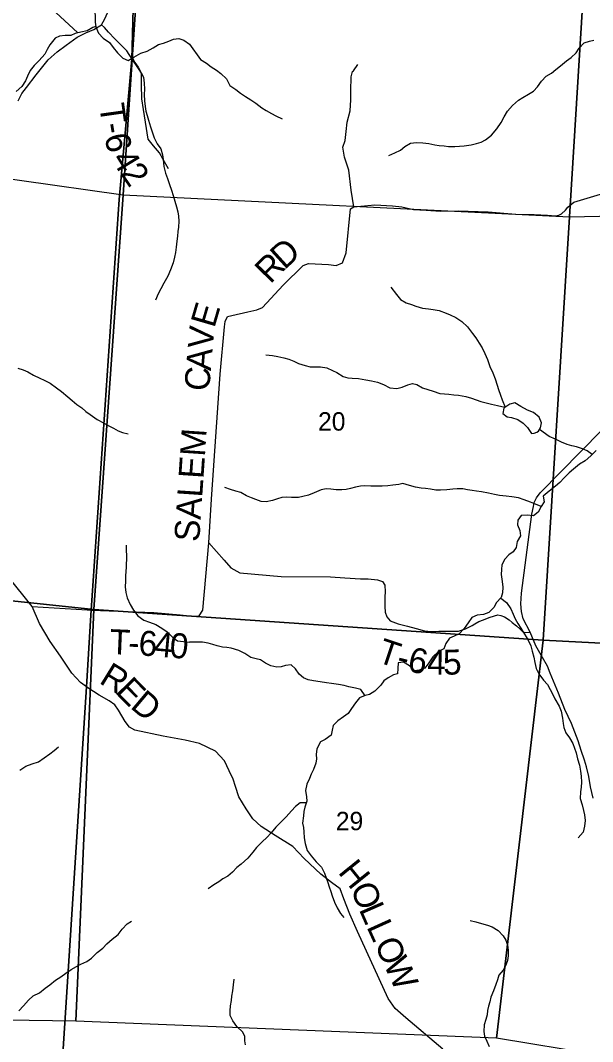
# Model space of a CAD drawing. Extents: x 0 to 40.8, y 0 to 22.
# Drawn here: x 3.414 to 4.714, y 18.326 to 20.647 of the extents above; entities that cross this region are included whole.
import ezdxf

# ---------------------------------------------------------------- set-up
doc = ezdxf.new("R2010")
doc.units = 0
for name, color, linetype in [('Default', 7, 'Continuous'), ('GM_X_County_Road', 7, 'Continuous'), ('GM_X_County_Road_Text', 7, 'Continuous'), ('GM_X_Minor_Lake', 7, 'Continuous'), ('GM_X_Minor_River', 7, 'Continuous'), ('GM_X_Section', 7, 'Continuous'), ('GM_X_Section_Text', 7, 'Continuous'), ('GM_X_State_Route', 7, 'Continuous'), ('GM_X_Township_Road', 7, 'Continuous'), ('GM_X_Township_Road_Text', 7, 'Continuous')]:
    doc.layers.add(name, color=color, linetype=linetype)

msp = doc.modelspace()

# ---------------------------------------------------------------- linework, layer by layer
at = {"layer": 'Default'}
msp.add_lwpolyline([(3.6829, 20.9), (2.1, 20.9), (2.1, 17.4153), (2.4594, 17.3966), (2.8463, 17.3693), (2.8484, 17.3691), (3.1244, 17.3534), (3.4481, 17.3334), (3.5638, 19.132), (3.5742, 19.2945), (3.575, 19.3064), (3.6386, 20.2396), (3.6672, 20.5588), (3.6703, 20.6733)], close=True, dxfattribs=at)
msp.add_lwpolyline([(7.7204, 20.9), (3.6829, 20.9), (3.6703, 20.6733), (3.6672, 20.5588), (3.6386, 20.2396), (3.575, 19.3064), (3.5742, 19.2945), (3.5638, 19.132), (3.4481, 17.3334), (4.5348, 17.2687), (4.8294, 17.2493), (5.3407, 17.2146), (5.6278, 17.197), (6.1785, 17.166), (6.9172, 17.1197)], dxfattribs=at)
at = {"layer": 'GM_X_County_Road'}
for points in [[(3.6903, 20.9), (2.7446, 20.9), (2.7045, 20.3832), (3.6475, 20.2502)], [(4.7052, 20.9), (3.6903, 20.9), (3.6475, 20.2502), (4.6616, 20.2002)], [(5.7251, 20.9), (4.7052, 20.9), (4.6616, 20.2002), (5.209, 20.2119), (5.6669, 20.1827)]]:
    msp.add_lwpolyline(points, close=True, dxfattribs=at)
for points in [[(3.4084, 20.464), (3.4169, 20.4805), (3.4276, 20.4943), (3.4494, 20.5231), (3.4772, 20.5566), (3.4975, 20.5749), (3.5175, 20.59), (3.5432, 20.6081), (3.5625, 20.6182), (3.5807, 20.6257), (3.5982, 20.6368), (3.606, 20.6499), (3.6118, 20.6641), (3.6169, 20.6889), (3.619, 20.7128), (3.6158, 20.741), (3.6108, 20.78), (3.6063, 20.8149), (3.6057, 20.8342), (3.608, 20.8547), (3.6128, 20.8672), (3.6204, 20.8813), (3.6297, 20.8957), (3.631, 20.9)], [(3.5673, 19.1293), (3.564, 19.1315), (3.5503, 19.1417), (3.531, 19.1627), (3.5049, 19.2019), (3.4817, 19.2352), (3.4576, 19.2755), (3.4403, 19.3142), (3.3856, 19.3835)], [(4.374, 18.3086), (4.29, 18.3799), (4.2657, 18.4005), (4.2493, 18.4238), (4.1803, 18.5758), (4.1625, 18.6154), (4.1492, 18.65), (4.1409, 18.6725), (4.1211, 18.6874), (4.0968, 18.7061), (4.0588, 18.7416), (4.0333, 18.769), (3.9926, 18.7943), (3.9607, 18.8145), (3.9424, 18.8317), (3.9269, 18.8549), (3.9102, 18.882), (3.9026, 18.9052), (3.8973, 18.922), (3.8886, 18.9406), (3.8779, 18.9635), (3.8571, 18.9856), (3.8211, 19.0031), (3.7883, 19.0106), (3.7386, 19.02), (3.6739, 19.0336), (3.6616, 19.04), (3.6522, 19.0528), (3.6371, 19.0785), (3.6287, 19.0907), (3.6152, 19.1004), (3.5929, 19.1126), (3.5673, 19.1293)]]:
    msp.add_lwpolyline(points, dxfattribs=at)
at = {"layer": 'GM_X_Minor_Lake'}
for points in [[(4.5956, 19.7204), (4.5984, 19.7321), (4.5931, 19.7447), (4.5799, 19.755), (4.5663, 19.7604), (4.5513, 19.7688), (4.5377, 19.7773), (4.5259, 19.7743), (4.5126, 19.7656), (4.5099, 19.7531), (4.5201, 19.7455), (4.5299, 19.7443), (4.5443, 19.7393), (4.5563, 19.7313), (4.5665, 19.721), (4.5751, 19.7076)], [(4.5751, 19.7076), (4.5812, 19.7081), (4.5872, 19.7103), (4.5911, 19.7129), (4.5956, 19.7204)]]:
    msp.add_lwpolyline(points, dxfattribs=at)
at = {"layer": 'GM_X_Minor_River'}
for points in [[(3.2517, 20.805), (3.2623, 20.8063), (3.2737, 20.8045), (3.2835, 20.8031), (3.2936, 20.7998), (3.3045, 20.7972), (3.3151, 20.7939), (3.3278, 20.7871), (3.3382, 20.7811), (3.3479, 20.7748), (3.3576, 20.7674), (3.3683, 20.7595), (3.3784, 20.752), (3.39, 20.7464), (3.4, 20.7401), (3.4108, 20.7322), (3.4209, 20.7255), (3.4324, 20.718), (3.4424, 20.7094), (3.4539, 20.7004), (3.4647, 20.691), (3.4747, 20.6824), (3.5442, 20.618)], [(3.5816, 20.6715), (3.5833, 20.6653), (3.5835, 20.6555), (3.584, 20.6422), (3.5849, 20.6319), (3.5911, 20.6174), (3.6019, 20.6061), (3.6165, 20.596), (3.625, 20.5852), (3.6346, 20.5725), (3.6465, 20.5605), (3.6589, 20.5553), (3.6716, 20.563), (3.6873, 20.5722), (3.7018, 20.5768), (3.7152, 20.5842), (3.7279, 20.5915), (3.7389, 20.5947), (3.7511, 20.599), (3.7615, 20.6038), (3.774, 20.6054), (3.7853, 20.6014), (3.798, 20.5924)], [(3.5849, 20.6325), (3.5781, 20.6302), (3.5658, 20.6232), (3.551, 20.6197), (3.538, 20.6165), (3.5281, 20.6125), (3.5152, 20.612), (3.5026, 20.6104), (3.4931, 20.606), (3.4806, 20.5911), (3.4744, 20.5806), (3.4692, 20.57), (3.4568, 20.5551), (3.4452, 20.5443), (3.4359, 20.5324), (3.43, 20.5196), (3.4252, 20.509), (3.417, 20.4967), (3.4039, 20.4848)], [(3.798, 20.5924), (3.8228, 20.5578), (3.8371, 20.549), (3.8477, 20.5414), (3.8598, 20.5333), (3.8696, 20.5261), (3.882, 20.5135), (3.8898, 20.4986), (3.9038, 20.4898), (3.914, 20.4814), (3.9253, 20.4738), (3.9377, 20.4657), (3.9486, 20.4585), (3.9626, 20.4478), (3.9724, 20.442), (3.9848, 20.4351), (3.9947, 20.4297), (4.0086, 20.4232)], [(4.2512, 20.3395), (4.2648, 20.3458), (4.2774, 20.3518), (4.2873, 20.3597), (4.3002, 20.3672), (4.3142, 20.3691), (4.3286, 20.3686), (4.3418, 20.3666), (4.3554, 20.3635), (4.3656, 20.3619), (4.3766, 20.3611), (4.3868, 20.3603), (4.4008, 20.3602), (4.4118, 20.3605), (4.4221, 20.3612), (4.438, 20.3634), (4.4501, 20.3667), (4.4611, 20.3697), (4.4706, 20.3753), (4.4843, 20.3855), (4.4969, 20.4002), (4.5061, 20.4142), (4.5133, 20.4274), (4.521, 20.4406), (4.5324, 20.4535), (4.5457, 20.4651), (4.556, 20.4715), (4.5685, 20.479), (4.5796, 20.4858), (4.5887, 20.4956), (4.5983, 20.5084), (4.6089, 20.5197), (4.6211, 20.5269), (4.631, 20.5352), (4.6413, 20.5431), (4.655, 20.5547), (4.6652, 20.5626), (4.6767, 20.5732), (4.6835, 20.5834), (4.695, 20.5955), (4.7071, 20.5992), (4.7173, 20.6014)], [(3.6687, 20.5613), (3.674, 20.5512), (3.6814, 20.5401), (3.6883, 20.5274), (3.6935, 20.5178), (3.6951, 20.5041), (3.6956, 20.49), (3.6953, 20.4783), (3.6962, 20.4635), (3.6975, 20.4505), (3.6992, 20.4399), (3.7016, 20.4303), (3.7052, 20.42), (3.7098, 20.4044), (3.713, 20.3933), (3.7181, 20.3799), (3.725, 20.3657), (3.7332, 20.3549), (3.7371, 20.3408), (3.738, 20.3306), (3.7396, 20.3146), (3.7435, 20.2993), (3.7478, 20.2871), (3.7528, 20.2737), (3.7571, 20.2607), (3.7607, 20.2489), (3.765, 20.2355), (3.7689, 20.2225), (3.7717, 20.2115), (3.7731, 20.2019), (3.7736, 20.1902), (3.7729, 20.1769), (3.772, 20.167), (3.771, 20.1561), (3.7697, 20.1451), (3.7679, 20.1314), (3.7665, 20.1193), (3.764, 20.1084), (3.7611, 20.0959), (3.7551, 20.0797), (3.7488, 20.0654), (3.7398, 20.0493), (3.7327, 20.0365), (3.7268, 20.0248), (3.7212, 20.0105)], [(4.2554, 20.0399), (4.2685, 20.0235), (4.2779, 20.012), (4.2907, 20.0048), (4.3024, 20.0009), (4.3126, 19.9974), (4.3278, 19.9928), (4.3414, 19.9912), (4.3516, 19.9896), (4.3652, 19.9872), (4.3811, 19.9811), (4.3909, 19.9776), (4.4037, 19.9711), (4.4173, 19.9619), (4.4301, 19.9501), (4.4414, 19.9352), (4.4489, 19.9249), (4.4567, 19.9131), (4.4631, 19.9021), (4.4691, 19.8895), (4.4754, 19.8758), (4.481, 19.8603), (4.4874, 19.8454), (4.493, 19.8317), (4.4974, 19.8173), (4.5004, 19.8074), (4.5048, 19.7949), (4.5089, 19.7842), (4.5154, 19.7674)], [(3.9716, 19.8864), (3.9871, 19.8848), (3.9992, 19.8829), (4.0128, 19.8794), (4.0238, 19.8767), (4.0351, 19.872), (4.046, 19.867), (4.0612, 19.862), (4.0721, 19.8589), (4.0831, 19.8589), (4.096, 19.8592), (4.1104, 19.8568), (4.1228, 19.8507), (4.1326, 19.846), (4.1477, 19.8372), (4.1579, 19.8341), (4.1681, 19.8333), (4.1821, 19.8328), (4.1992, 19.8297), (4.2116, 19.827), (4.2256, 19.8242), (4.2392, 19.8192), (4.2532, 19.8116), (4.2691, 19.8096), (4.2812, 19.8129), (4.2945, 19.8185), (4.3047, 19.8211), (4.3146, 19.8188), (4.3278, 19.8115), (4.3399, 19.808), (4.3519, 19.8038), (4.3667, 19.7984), (4.3773, 19.7976), (4.3875, 19.7967), (4.3992, 19.7959), (4.4094, 19.7947), (4.4265, 19.7916), (4.4393, 19.7881), (4.4499, 19.7842), (4.4601, 19.7807), (4.4726, 19.7776), (4.4843, 19.7745), (4.4983, 19.771), (4.515, 19.7672)], [(3.4081, 19.8561), (3.4201, 19.8525), (3.4307, 19.8481), (3.4438, 19.8406), (3.4577, 19.8335), (3.4675, 19.8288), (3.4817, 19.8224), (3.4956, 19.8115), (3.5075, 19.8033), (3.5213, 19.7913), (3.5318, 19.7827), (3.5422, 19.7738), (3.5531, 19.766), (3.5628, 19.7578), (3.5725, 19.7512), (3.5886, 19.7391), (3.6025, 19.7316), (3.616, 19.7241), (3.6257, 19.7194), (3.6362, 19.7139), (3.646, 19.7099), (3.6585, 19.7066)], [(4.7136, 19.6601), (4.7017, 19.6686), (4.6915, 19.6728), (4.6775, 19.6771), (4.6669, 19.6794), (4.6563, 19.6825), (4.6439, 19.6879), (4.6299, 19.6944), (4.6156, 19.7009), (4.5935, 19.7169)], [(4.7221, 19.6688), (4.7103, 19.6568), (4.697, 19.6455), (4.6841, 19.638), (4.6711, 19.6267), (4.6609, 19.6184), (4.6498, 19.6067), (4.6399, 19.5965), (4.6296, 19.5882), (4.6156, 19.5762), (4.6019, 19.5653), (4.604, 19.5527), (4.5975, 19.5421), (4.5903, 19.5285), (4.58, 19.5203), (4.5652, 19.5219), (4.552, 19.5212), (4.544, 19.5106), (4.5439, 19.5004), (4.5487, 19.4875), (4.5506, 19.4753), (4.5429, 19.4621), (4.5406, 19.4488), (4.5337, 19.439), (4.5238, 19.4315), (4.5146, 19.4217), (4.5077, 19.4092), (4.5069, 19.3986), (4.5065, 19.3872), (4.509, 19.3716), (4.5101, 19.3584), (4.5092, 19.3455), (4.5065, 19.3349), (4.4955, 19.3239), (4.4901, 19.3122), (4.4787, 19.3005), (4.4662, 19.2961), (4.4521, 19.2946), (4.4396, 19.2898), (4.4312, 19.2773), (4.422, 19.2645), (4.411, 19.2524), (4.3996, 19.2468), (4.3893, 19.2423), (4.3809, 19.2302), (4.3759, 19.2185), (4.3634, 19.2117), (4.3508, 19.2), (4.342, 19.1864), (4.3329, 19.1744), (4.32, 19.1699), (4.3086, 19.1684), (4.2985, 19.1799), (4.2845, 19.1879), (4.2724, 19.1861), (4.2719, 19.1732), (4.2711, 19.1615), (4.2616, 19.1589), (4.2495, 19.1525), (4.2399, 19.1457), (4.2327, 19.1359), (4.2197, 19.1219), (4.2072, 19.1144), (4.1977, 19.1118), (4.1848, 19.1066), (4.1756, 19.0953), (4.1665, 19.0824), (4.1588, 19.0715), (4.1478, 19.0636), (4.1353, 19.0549), (4.1246, 19.044), (4.1223, 19.033), (4.1203, 19.0217), (4.1062, 19.0119), (4.096, 19.0066), (4.0875, 18.9908), (4.0863, 18.9779)], [(4.5973, 19.5417), (4.5847, 19.5468), (4.5734, 19.5518), (4.5586, 19.5572), (4.5462, 19.5618), (4.5307, 19.5638), (4.5178, 19.565), (4.5027, 19.567), (4.4913, 19.5693), (4.4773, 19.5717), (4.4618, 19.5748), (4.4501, 19.5768), (4.4403, 19.5784), (4.4297, 19.5799), (4.4195, 19.5819), (4.4066, 19.582), (4.3968, 19.5813), (4.3827, 19.5798), (4.3687, 19.5788), (4.3577, 19.5789), (4.346, 19.5808), (4.3347, 19.5824), (4.3245, 19.5832), (4.3116, 19.5856), (4.2984, 19.5894), (4.2832, 19.5937), (4.2738, 19.5919), (4.2605, 19.5904), (4.2488, 19.589), (4.2359, 19.5879), (4.2226, 19.5876), (4.2101, 19.5877), (4.1969, 19.5885), (4.187, 19.5882), (4.1753, 19.586), (4.1639, 19.583), (4.1544, 19.5801), (4.1442, 19.5794), (4.1313, 19.5794), (4.1196, 19.5814), (4.109, 19.5819), (4.0973, 19.5797), (4.0813, 19.5725), (4.0684, 19.5673), (4.0555, 19.5644), (4.046, 19.5621), (4.0298, 19.5622), (4.0184, 19.5631), (4.0082, 19.5624), (3.9979, 19.5594), (3.9866, 19.5557), (3.9725, 19.5523), (3.9608, 19.5532), (3.9487, 19.5578), (3.9389, 19.5616), (3.9279, 19.5663), (3.9147, 19.5732), (3.9034, 19.5766), (3.8913, 19.5805), (3.8785, 19.5848)], [(3.6544, 19.4539), (3.6545, 19.4436), (3.6546, 19.4288), (3.6541, 19.4038), (3.6536, 19.3943), (3.653, 19.3841), (3.6524, 19.3723), (3.6522, 19.3594), (3.6534, 19.3465), (3.6566, 19.3339), (3.6635, 19.3193), (3.6708, 19.3063), (3.6808, 19.2936), (3.6943, 19.2834), (3.7071, 19.2786), (3.7214, 19.2734), (3.7349, 19.2655), (3.7476, 19.2566), (3.7599, 19.2438), (3.7707, 19.2364), (3.7843, 19.2346), (3.7983, 19.2332)], [(4.5054, 19.3337), (4.5182, 19.3238), (4.5283, 19.3093), (4.5339, 19.2968), (4.5384, 19.2861), (4.544, 19.2755), (4.5508, 19.2652), (4.5598, 19.2519), (4.5673, 19.2393), (4.5736, 19.2249), (4.5769, 19.2131), (4.581, 19.1994), (4.5828, 19.1873), (4.5862, 19.1732), (4.5921, 19.1614), (4.6027, 19.1473), (4.6117, 19.137), (4.6177, 19.126), (4.6229, 19.1157), (4.6285, 19.1043), (4.6379, 19.0876), (4.6431, 19.0769), (4.646, 19.0606), (4.6475, 19.0488), (4.6489, 19.0394), (4.6534, 19.0276), (4.6617, 19.0162), (4.6692, 19.0028), (4.6733, 18.9926), (4.6766, 18.9816), (4.6803, 18.9683), (4.6847, 18.9538), (4.6869, 18.9402), (4.688, 18.9288), (4.6891, 18.9155), (4.6882, 18.9041), (4.6866, 18.8931), (4.6858, 18.8783), (4.6902, 18.8635), (4.6932, 18.851), (4.6958, 18.8411), (4.6972, 18.8278), (4.696, 18.815), (4.6925, 18.8017), (4.6818, 18.7885)], [(4.197, 19.1115), (4.1876, 19.1256), (4.1755, 19.129), (4.1604, 19.1322), (4.1498, 19.1349), (4.1369, 19.1369), (4.121, 19.1392), (4.1097, 19.1408), (4.0953, 19.1432), (4.0798, 19.1452), (4.0677, 19.1475), (4.0575, 19.1525), (4.0477, 19.1609), (4.0391, 19.1727), (4.0289, 19.1815), (4.0164, 19.1804), (4.0065, 19.1775), (3.9963, 19.1764), (3.9827, 19.1795), (3.971, 19.186), (3.9597, 19.1929), (3.9495, 19.1952), (3.9378, 19.1987), (3.9242, 19.2075), (3.9106, 19.2144), (3.8928, 19.2195), (3.883, 19.221), (3.8732, 19.2222), (3.8611, 19.2253), (3.8513, 19.2281), (3.8407, 19.2312), (3.8278, 19.2335), (3.7983, 19.2332)], [(3.4125, 18.9428), (3.4259, 18.9513), (3.4404, 18.9571), (3.4553, 18.9617), (3.468, 18.9702), (3.4807, 18.9794), (3.4903, 18.9872), (3.5007, 18.9954)], [(4.0863, 18.9779), (4.0866, 18.9684), (4.0854, 18.9582), (4.0801, 18.9438), (4.0747, 18.9336), (4.0705, 18.9237), (4.0647, 18.9109), (4.0616, 18.8961), (4.0641, 18.8821), (4.0645, 18.8718), (4.0606, 18.8582), (4.0579, 18.8484), (4.0571, 18.8385), (4.0551, 18.8218), (4.0573, 18.8123), (4.0576, 18.8021), (4.0586, 18.7884), (4.0612, 18.7755), (4.0653, 18.7599), (4.0743, 18.7478), (4.0859, 18.734), (4.0984, 18.7218), (4.1051, 18.7085), (4.1122, 18.6869), (4.1155, 18.677), (4.1192, 18.6663), (4.1226, 18.6565), (4.1278, 18.6428), (4.1338, 18.6295), (4.1416, 18.6169), (4.1491, 18.6074)], [(4.0635, 18.8683), (4.0493, 18.8681), (4.039, 18.8602), (4.0303, 18.85), (4.0177, 18.8361), (3.9944, 18.8131), (3.9841, 18.7999), (3.9742, 18.7893), (3.9636, 18.7795), (3.9502, 18.7667), (3.9418, 18.7561), (3.9304, 18.7426), (3.9155, 18.729), (3.9056, 18.7211), (3.8957, 18.7109), (3.8855, 18.7019), (3.8741, 18.6951), (3.8646, 18.6887), (3.8532, 18.6816), (3.8402, 18.6729)], [(3.4099, 18.3955), (3.4211, 18.4071), (3.4319, 18.4198), (3.4428, 18.4298), (3.4569, 18.4367), (3.47, 18.4467), (3.4808, 18.4549), (3.4935, 18.4652), (3.5058, 18.4726), (3.5169, 18.4811), (3.5292, 18.4892), (3.5411, 18.4962), (3.5514, 18.5017), (3.5645, 18.5079), (3.5752, 18.5149), (3.5883, 18.5279), (3.6014, 18.5379), (3.6103, 18.548), (3.6227, 18.558), (3.6358, 18.5687), (3.6451, 18.5811), (3.6563, 18.593), (3.6663, 18.5992)], [(4.4357, 18.6011), (4.4489, 18.5976), (4.4618, 18.5937), (4.4754, 18.5899), (4.486, 18.586), (4.4995, 18.5784), (4.5108, 18.5658), (4.5172, 18.5559), (4.5209, 18.5449), (4.5227, 18.5335), (4.5227, 18.5202), (4.5207, 18.51), (4.5172, 18.499), (4.5111, 18.488), (4.5012, 18.4763), (4.4981, 18.4657), (4.4946, 18.4555), (4.4892, 18.4411), (4.4831, 18.4264), (4.4804, 18.4162), (4.4773, 18.4063), (4.4757, 18.3965), (4.4745, 18.3866), (4.4718, 18.3756), (4.4679, 18.3639), (4.4667, 18.3484), (4.4689, 18.3377), (4.4741, 18.3263), (4.4794, 18.3145)], [(3.9255, 18.3178), (3.924, 18.3273), (3.9237, 18.3372), (3.9196, 18.3467), (3.9057, 18.3597), (3.8963, 18.3726), (3.8907, 18.3852), (3.8904, 18.3954), (3.8912, 18.4068), (3.8935, 18.4193), (3.8944, 18.4288), (3.8963, 18.4409), (3.8979, 18.4545)], [(3.8979, 18.4545), (3.8995, 18.4674)]]:
    msp.add_lwpolyline(points, dxfattribs=at)
at = {"layer": 'GM_X_Section'}
for points in [[(2.7045, 20.3832), (3.6475, 20.2502), (3.5805, 19.3077), (2.6264, 19.4085)], [(3.6475, 20.2502), (4.6616, 20.2002), (4.6019, 19.2378), (3.5805, 19.3077)], [(4.6616, 20.2002), (5.209, 20.2119), (5.6669, 20.1827), (5.5995, 19.1863), (4.6019, 19.2378)], [(2.6264, 19.4085), (3.5805, 19.3077), (3.54, 18.3719), (2.5343, 18.3862)], [(3.5805, 19.3077), (4.6019, 19.2378), (4.4961, 18.3336), (3.54, 18.3719)]]:
    msp.add_lwpolyline(points, close=True, dxfattribs=at)
msp.add_lwpolyline([(5.1222, 18.2458), (4.9546, 18.2574), (4.4961, 18.3336), (4.6019, 19.2378), (5.5995, 19.1863), (5.5864, 18.978)], dxfattribs=at)
at = {"layer": 'GM_X_State_Route'}
msp.add_lwpolyline([(4.7157, 18.8789), (4.7097, 18.9044), (4.7057, 18.9284), (4.7006, 18.9497), (4.6961, 18.965), (4.6886, 18.9874), (4.6812, 19.0088), (4.6666, 19.0488), (4.6512, 19.0801), (4.637, 19.1178), (4.6176, 19.1628), (4.612, 19.1785), (4.6007, 19.1987), (4.5853, 19.2247), (4.5726, 19.2559), (4.5561, 19.2861), (4.5524, 19.3032), (4.5514, 19.3204), (4.5527, 19.3451), (4.5763, 19.5243), (4.5802, 19.5414), (4.5814, 19.5505), (4.5864, 19.5615), (4.5949, 19.5728), (4.8739, 19.8562)], dxfattribs=at)
at = {"layer": 'GM_X_Township_Road'}
msp.add_line((3.4403, 19.3142), (3.5656, 19.3065), dxfattribs=at)
for points in [[(3.6675, 20.5583), (3.6555, 20.5777), (3.6282, 20.6045), (3.6141, 20.6199), (3.605, 20.6301), (3.5982, 20.6368)], [(3.7505, 20.3089), (3.7381, 20.3307), (3.7298, 20.3459), (3.7166, 20.3612), (3.7045, 20.3768), (3.6979, 20.4152), (3.6935, 20.4442), (3.6899, 20.4685), (3.6894, 20.5011), (3.6894, 20.5264), (3.6826, 20.5373), (3.6675, 20.5583)], [(4.1718, 20.2232), (4.1654, 20.2605), (4.1601, 20.3061), (4.1507, 20.3354), (4.1469, 20.3583), (4.1522, 20.3739), (4.1542, 20.394), (4.1565, 20.4149), (4.1634, 20.4411), (4.1649, 20.4662), (4.165, 20.4868), (4.1654, 20.518), (4.1686, 20.5307), (4.1706, 20.5322), (4.181, 20.5461)], [(3.5656, 19.3065), (3.5753, 19.3059), (3.7167, 19.3008), (3.7773, 19.2954), (3.806, 19.2924), (3.8202, 19.2934), (3.8286, 19.3063), (3.8422, 19.4588), (3.8484, 19.5585), (3.8675, 19.8425), (3.8776, 19.9498), (3.8795, 19.9619), (3.8848, 19.9733), (3.894, 19.9756), (3.9309, 19.9842), (3.9511, 19.9884), (3.964, 19.994), (4.0109, 20.0445), (4.0563, 20.0896), (4.0685, 20.0941), (4.1141, 20.0921), (4.1316, 20.0898), (4.1461, 20.0954), (4.1545, 20.1186), (4.1642, 20.2179), (4.1718, 20.2232), (4.2194, 20.2272), (4.2593, 20.2248), (4.281, 20.2225), (4.3073, 20.2167), (4.3358, 20.2155), (4.3682, 20.2131), (4.4089, 20.2137), (4.477, 20.2112), (4.5398, 20.2061), (4.5816, 20.2052), (4.6121, 20.2036), (4.6296, 20.2021), (4.6376, 20.2036), (4.6437, 20.2066), (4.6528, 20.2153), (4.6578, 20.2221), (4.6715, 20.2331), (4.732, 20.2516)], [(3.8422, 19.4588), (3.8771, 19.4195), (3.8919, 19.402), (3.9129, 19.3913), (4.0068, 19.383), (4.1187, 19.3816), (4.1515, 19.3799), (4.1869, 19.3772), (4.2044, 19.3775), (4.2253, 19.3748), (4.2371, 19.3709), (4.2424, 19.3629), (4.2431, 19.3481), (4.2424, 19.3363), (4.2419, 19.3143), (4.2431, 19.3017), (4.2465, 19.2907), (4.2544, 19.2815), (4.2723, 19.2754), (4.2936, 19.2696), (4.313, 19.2646), (4.3324, 19.2592), (4.3473, 19.2573), (4.3648, 19.258), (4.38, 19.2587), (4.3975, 19.2583), (4.4093, 19.2586), (4.4257, 19.2635), (4.4409, 19.2715), (4.4466, 19.2752), (4.4558, 19.2802), (4.4664, 19.2843), (4.4794, 19.2892), (4.4916, 19.293), (4.4992, 19.2956), (4.506, 19.2941), (4.5144, 19.291), (4.5243, 19.2841), (4.5315, 19.278), (4.5414, 19.2704), (4.5486, 19.2635), (4.5558, 19.257), (4.5612, 19.2551), (4.5726, 19.2559)]]:
    msp.add_lwpolyline(points, dxfattribs=at)

# ---------------------------------------------------------------- texts
at = {"layer": 'GM_X_County_Road_Text'}
for s, rotation, p in [('R', 328.2751, (3.5905, 19.1417)), ('E', 314.5061, (3.6274, 19.1194)), ('D', 319.8874, (3.6614, 19.0852)), ('H', 308.9511, (4.1341, 18.71)), ('O', 291.4821, (4.1632, 18.675)), ('L', 293.6276, (4.1824, 18.6264)), ('L', 294.4072, (4.1998, 18.5867)), ('O', 294.4272, (4.2174, 18.5479)), ('W', 294.7991, (4.2382, 18.5021))]:
    msp.add_text(s, height=0.0568, rotation=rotation, dxfattribs=at).set_placement(p)
at = {"layer": 'GM_X_Section_Text'}
for s, p in [('20', (4.0903, 19.7142)), ('29', (4.1307, 18.8059))]:
    msp.add_text(s, height=0.04186, rotation=0, dxfattribs=at).set_placement(p)
at = {"layer": 'GM_X_Township_Road_Text'}
for s, height, rotation, p in [('T', 0.0568, 278.0319, (3.5928, 20.4541)), ('-', 0.0568, 279.7853, (3.5991, 20.4102)), ('6', 0.0568, 283.7614, (3.6039, 20.383)), ('4', 0.0568, 301.2944, (3.6195, 20.3315)), ('2', 0.0568, 304.4075, (3.6395, 20.2988)), ('D', 0.0568, 42.3073, (4.0139, 20.0784)), ('R', 0.0568, 45.345, (3.9817, 20.0458)), ('E', 0.0568, 73.7461, (3.8545, 19.9458)), ('V', 0.0568, 85.0249, (3.8507, 19.8989)), ('A', 0.0568, 85.1875, (3.8465, 19.8492)), ('C', 0.0568, 85.178, (3.8426, 19.8026)), ('SALEM', 0.05682, 86.1574, (3.8201, 19.4603)), ('T', 0.0568, 357.5177, (3.6157, 19.2064)), ('6', 0.0568, 356.7405, (3.6812, 19.2035)), ('4', 0.0568, 354.9191, (3.7157, 19.2016)), ('0', 0.0568, 355.8611, (3.7516, 19.1984)), ('T', 0.0568, 341.5149, (4.2216, 19.1893)), ('-', 0.0568, 357.3528, (3.6581, 19.2046)), ('6', 0.0568, 347.9316, (4.2912, 19.1681)), ('-', 0.0568, 345.4293, (4.266, 19.1746)), ('4', 0.0568, 359.6588, (4.338, 19.1594)), ('5', 0.0568, 1.4192, (4.3749, 19.1592))]:
    msp.add_text(s, height=height, rotation=rotation, dxfattribs=at).set_placement(p)

doc.saveas('drawing.dxf')
